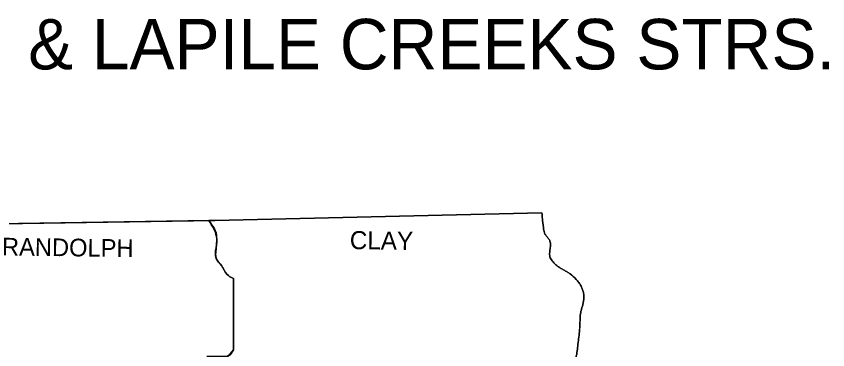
# Model space of a CAD drawing. Extents: x 185 to 5012, y 113 to 2127.
# Drawn here: x 3121.8 to 3310.1, y 1957.5 to 2035 of the extents above; entities that cross this region are included whole.
import ezdxf

# ---------------------------------------------------------------- set-up
doc = ezdxf.new("R2010")
doc.units = 0
for name, color, linetype in [('Default', 7, 'Continuous'), ('R_Border', 7, 'Continuous'), ('R_No Plot', 7, 'Continuous')]:
    doc.layers.add(name, color=color, linetype=linetype)

msp = doc.modelspace()

# ---------------------------------------------------------------- linework, layer by layer
at = {"layer": 'Default'}
for points in [[(2707.02, 1984.77), (2865.23, 1984.67), (3004.07, 1984.97), (3167.85, 1987.51), (3243.78, 1989.27)], [(3172.16, 1974.01), (3172.16, 1957.47)]]:
    msp.add_lwpolyline(points, dxfattribs=at)
for points in [[(3243.78, 1989.27), (3243.86, 1988.19), (3243.97, 1987.11), (3244.11, 1986.04), (3244.27, 1984.97), (3244.49, 1984.36), (3244.89, 1983.81), (3245.32, 1983.28), (3245.64, 1982.72), (3245.76, 1981.72), (3245.64, 1980.65), (3245.56, 1979.59), (3245.64, 1979.08), (3245.83, 1978.61), (3246.57, 1977.64), (3247.49, 1976.85), (3248.19, 1976.38), (3248.92, 1975.97), (3249.64, 1975.56), (3250.33, 1975.08), (3251.74, 1973.83), (3252.35, 1973.1), (3252.62, 1972.69), (3252.88, 1972.25), (3253.23, 1971.42), (3253.44, 1970.58), (3253.51, 1969.75), (3253.46, 1968.92), (3253.29, 1968.07), (3253.05, 1967.21), (3252.82, 1966.36), (3252.68, 1965.5), (3252.63, 1964.55), (3252.59, 1963.59), (3252.55, 1962.63), (3252.48, 1961.68), (3252.09, 1958.35), (3251.91, 1956.82), (3251.76, 1956.07), (3251.65, 1955.69), (3251.51, 1955.32), (3250.49, 1953.96), (3249.16, 1952.87), (3248.6, 1952.43), (3248.03, 1952), (3247.46, 1951.57), (3246.91, 1951.11), (3244.85, 1949.06), (3244.47, 1948.53), (3244.14, 1947.96), (3243.8, 1947.4), (3243.38, 1946.91), (3240.84, 1944.56), (3238.3, 1942.11), (3236.24, 1939.96), (3235.68, 1939.31), (3235.16, 1938.63), (3234.66, 1937.93), (3234.19, 1937.22), (3233.89, 1936.48), (3233.74, 1935.67), (3233.58, 1934.87), (3233.43, 1934.51), (3233.21, 1934.19), (3232.67, 1933.63), (3232.09, 1933.1), (3231.51, 1932.58), (3230.96, 1932.03), (3229.2, 1930.08), (3226.85, 1927.43), (3226.46, 1926.83), (3226.2, 1926.15), (3225.96, 1925.45), (3225.68, 1924.79), (3225.15, 1924.02), (3224.54, 1923.29), (3223.93, 1922.55), (3223.43, 1921.76), (3223.21, 1921.06), (3223.16, 1920.3), (3223.11, 1919.54), (3222.94, 1918.82), (3222.62, 1918.22), (3222.23, 1917.64), (3221.83, 1917.06), (3221.47, 1916.48), (3221.35, 1916.1)], [(3166.47, 1987.49), (3168.24, 1983.79), (3168.15, 1981.15), (3168.15, 1978.7), (3169.42, 1977.04), (3170.69, 1974.99), (3172.16, 1974.01)]]:
    msp.add_spline(points, degree=3, dxfattribs=at)
at = {"layer": 'R_No Plot'}
for p, q in [((3166.47, 1987.49), (3094.06, 1986.36)), ((3172.16, 1957.47), (3172.16, 1974.01)), ((3172.16, 1974.01), (3172.16, 1957.47))]:
    msp.add_line(p, q, dxfattribs=at)
msp.add_lwpolyline([(3243.78, 1989.27), (3167.85, 1987.51), (3166.47, 1987.49)], dxfattribs=at)
for points in [[(3252.6, 1963.71), (3252.63, 1964.55), (3252.68, 1965.5), (3252.82, 1966.36), (3253.05, 1967.21), (3253.29, 1968.07), (3253.46, 1968.92), (3253.51, 1969.75), (3253.44, 1970.58), (3253.23, 1971.42), (3252.88, 1972.25), (3252.62, 1972.69), (3252.35, 1973.1), (3251.74, 1973.83), (3250.33, 1975.08), (3249.64, 1975.56), (3248.92, 1975.97), (3248.19, 1976.38), (3247.49, 1976.85), (3246.57, 1977.64), (3245.83, 1978.61), (3245.64, 1979.08), (3245.56, 1979.59), (3245.64, 1980.65), (3245.76, 1981.72), (3245.64, 1982.72), (3245.32, 1983.28), (3244.89, 1983.81), (3244.49, 1984.36), (3244.27, 1984.97), (3244.11, 1986.04), (3243.97, 1987.11), (3243.86, 1988.19), (3243.78, 1989.27)], [(3172.16, 1974.01), (3170.69, 1974.99), (3169.42, 1977.04), (3168.15, 1978.7), (3168.15, 1981.15), (3168.24, 1983.79), (3166.47, 1987.49)], [(3166.47, 1987.49), (3166.74, 1987.12), (3167.01, 1986.75), (3167.27, 1986.37), (3167.52, 1985.99)], [(3168.15, 1978.7), (3168.32, 1978.27), (3168.63, 1977.89), (3168.98, 1977.54), (3169.16, 1977.36), (3169.32, 1977.17)], [(3171.59, 1974.36), (3171.88, 1974.19), (3172.16, 1974.01)], [(3241.97, 1945.6), (3243.38, 1946.91), (3243.8, 1947.4), (3244.14, 1947.96), (3244.47, 1948.53), (3244.85, 1949.06), (3246.91, 1951.11), (3247.46, 1951.57), (3248.03, 1952), (3248.6, 1952.43), (3249.16, 1952.87), (3250.49, 1953.96), (3251.51, 1955.32), (3251.65, 1955.69), (3251.76, 1956.07), (3251.91, 1956.82), (3252.09, 1958.35), (3252.48, 1961.68), (3252.55, 1962.63), (3252.59, 1963.59), (3252.6, 1963.71)], [(3165.99, 1955.91), (3168.05, 1955.91), (3170.49, 1955.91), (3172.16, 1957.47)]]:
    msp.add_spline(points, degree=3, dxfattribs=at)
for points in [[(3167.52, 1985.99), (3167.93, 1985.3), (3168.22, 1984.57), (3168.24, 1983.79), (3168.27, 1982.91), (3168.16, 1982.03), (3168.15, 1981.15), (3168.13, 1980.34), (3167.99, 1979.52), (3168.15, 1978.7)], [(3169.32, 1977.17), (3169.35, 1977.13), (3169.39, 1977.09), (3169.42, 1977.04), (3169.86, 1976.39), (3170.08, 1975.56), (3170.66, 1975.01)], [(3170.66, 1975.01), (3170.67, 1975), (3170.68, 1974.99), (3170.69, 1974.99), (3170.96, 1974.74), (3171.27, 1974.55), (3171.59, 1974.36)], [(3172.16, 1957.47), (3171.77, 1956.78), (3171.25, 1955.91), (3170.49, 1955.91), (3169.68, 1955.91), (3168.86, 1955.91), (3168.05, 1955.91), (3167.36, 1955.91), (3166.68, 1955.91), (3165.99, 1955.91)]]:
    msp.add_open_spline(points, degree=3, dxfattribs=at)

# ---------------------------------------------------------------- texts
at = {"layer": 'Default'}
for s, height, rotation, p in [('RANDOLPH', 4.11, 359.2583, (3118.44, 1979.39)), ('CLAY', 4.207, 359.2258, (3199.16, 1980.86))]:
    msp.add_text(s, height=height, rotation=rotation, dxfattribs=at).set_placement(p)
at = {"layer": 'R_Border'}
msp.add_text('CORNIE BAYOU, HARPER & LAPILE CREEKS STRS. & APRRS. (S)', height=11.724, dxfattribs=at).set_placement((2925.91, 2022.61))

doc.saveas('drawing.dxf')
